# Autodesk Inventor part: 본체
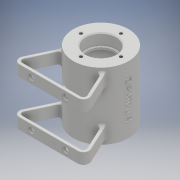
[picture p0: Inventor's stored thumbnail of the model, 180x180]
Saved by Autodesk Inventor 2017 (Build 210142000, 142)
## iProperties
Part Number: 본체
Material: 일반
Document SubType Name: Modeling
Designer: Administrator
Density: 1 g/cm^3
Appearance: 기본값
Author: Administrator
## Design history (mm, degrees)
sketch "스케치1"
  geometry: C1 r 29 at (0, 0); 1 further point
  constraints: 1 centre point, 1 coincident
  dimensions: "d0" = 58 diameter of C1
extrude "돌출1" new body sketch "스케치1" distance "d1" = 35; taper "d2" = 0 deg
hole "구멍1" diameter "d5" = 28; stored, may be unused: countersink angle "d9" = 90 deg, drill point angle "d11" = 118 deg; dims "d3" = 10, "d4" = 10, "d6" = 6, "d7" = 42, "d8" = 21, "d10" = 8
hole "구멍2" diameter "d14" = 28; stored, may be unused: countersink angle "d18" = 90 deg, drill point angle "d20" = 118 deg; dims "d12" = 10, "d13" = 10, "d15" = 6, "d16" = 32, "d17" = 12, "d19" = 8
fillet "모깎기1" dims "d21" = 3
sketch "스케치2"
  geometry: 2 further points
  constraints: 1 vertical alignment
  dimensions: "d23" = 21 distance of point (0, 21) point (0, 0)
hole "구멍3" sketch "스케치2" at (0, 21) diameter "d24" = 3.242; stored, may be unused: countersink angle "d28" = 90 deg, drill point angle "d30" = 118 deg; dims "d25" = 8, "d26" = 32, "d27" = 12, "d29" = 10
fillet "모깎기2" dims "d34" = 0.3
chamfer "모따기1" distance "d35" = 1; stored, may be unused: second distance "d36" = 2, angle "d37" = 45 deg
node "작업 평면1"
sketch "스케치3"
  geometry: L1 (-22.743, -17.993)-(-40, -55); L2 (-40, -55)-(40, -55); L3 (40, -55)-(22.743, -17.993); L4 (20.574, -20.438)-(35.291, -52); L5 (35.291, -52)-(-35.291, -52); L6 (-35.291, -52)-(-20.574, -20.438); A1 r 29 centre (0, 0) between (-22.743, -17.993) and (22.743, -17.993) reference; 2 further points
  constraints: 12 end point, 4 point on circle, 1 horizontal, 1 midpoint, 1 parallel, 1 vertical alignment
  dimensions: "d39" = 65 deg angle of L2 L1; "d40" = 65 deg angle of L2 L3; "d41" = 80 distance of L1.end L2.end; "d42" = 55 distance from line of L2 point (0, 0); "d43" = 3 distance between parallel lines of L3 L4; "d44" = 3 distance between parallel lines of L6 L1; "d45" = 3 distance between parallel lines of L2 L5
extrude "돌출2" join sketch "스케치3" distance "d46" = 12; taper "d47" = 0 deg
fillet "모깎기3" dims "d48" = 6
fillet "모깎기4" dims "d49" = 3
fillet "모깎기5" dims "d50" = 0.5
fillet "모깎기6" dims "d51" = 3
sketch "스케치7"
  geometry: 3 further points
  constraints: 1 horizontal alignment
  dimensions: "d91" = 24 vertical distance of point (12.582, -5.5) point (30.582, 18.5); "d92" = 18 horizontal distance of point (12.582, -5.5) point (30.582, 18.5); "d93" = 36 distance of point (48.582, -5.5) point (12.582, -5.5)
hole "구멍7" sketch "스케치7" at (12.582, -5.5), (48.582, -5.5) diameter "d94" = 6; stored, may be unused: countersink angle "d98" = 90 deg, drill point angle "d100" = 118 deg; dims "d95" = 12, "d96" = 32, "d97" = 12, "d99" = 32
node "작업 평면2"
sketch "스케치4"
  geometry: C1 r 5 at (0, 0); 1 further point
  constraints: 1 centre point, 1 coincident
  dimensions: "d53" = 10 diameter of C1
extrude "돌출3" join sketch "스케치4" stored distance "d54" = 12; taper "d55" = 0 deg
hole "구멍4" diameter "d58" = 5.188; stored, may be unused: countersink angle "d62" = 90 deg, drill point angle "d64" = 118 deg; dims "d59" = 6, "d60" = 32, "d61" = 12, "d63" = 8, "d79" = 10, "d80" = 10
hole "구멍5" diameter "d67" = 3; stored, may be unused: countersink angle "d71" = 90 deg, drill point angle "d73" = 118 deg; dims "d65" = 10, "d66" = 10, "d68" = 6, "d69" = 32, "d70" = 12, "d72" = 32
sketch "스케치5"
  geometry: L1 (0, 0)-(0, -21); L2 (0, 0)-(-10.945, -30.07); C1 r 21 at (0, 0) reference; C2 r 1.621 at (0, -21) reference; 1 further point
  constraints: 4 end point, 1 vertical
  dimensions: "d74" = 32 distance of L1.start L2.end; "d75" = 20 deg angle of L2 L1
node "작업 평면3"
sketch "스케치6"
  geometry: C1 r 6 at (0, 0); 1 further point
  constraints: 1 centre point, 1 coincident
  dimensions: "d76" = 12 diameter of C1
extrude "돌출4" join sketch "스케치6" stored distance "d77" = 12; taper "d78" = 0 deg
hole "구멍6" diameter "d83" = 5.188; stored, may be unused: countersink angle "d87" = 90 deg, drill point angle "d89" = 118 deg; dims "d81" = 10, "d82" = 10, "d84" = 12, "d85" = 32, "d86" = 12, "d88" = 32
fillet "모깎기7" dims "d90" = 1
node "작업 평면4"
sketch "스케치8"
  geometry: L1 (29, -35)-(29, 35) reference; L2 (29, 35)-(-29, 35) reference; 1 further point
  constraints: 1 other
  dimensions: "d105" = 35 distance from line of L2 point (0, 0); "d106" = 29 distance from line of L1 point (0, 0)
feature "엠보싱1" sketch "스케치8" dims "d103" = 0.5, "d104" = 0
node "솔리드1"
pattern_circular "원형 패턴1" dims angle "d32" = 360 deg
mirror "미러1"
other parameters: "d38" = -5, "d52" = 32, "d101" = 57.75
